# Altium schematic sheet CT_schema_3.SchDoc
size 208 x 169 mm
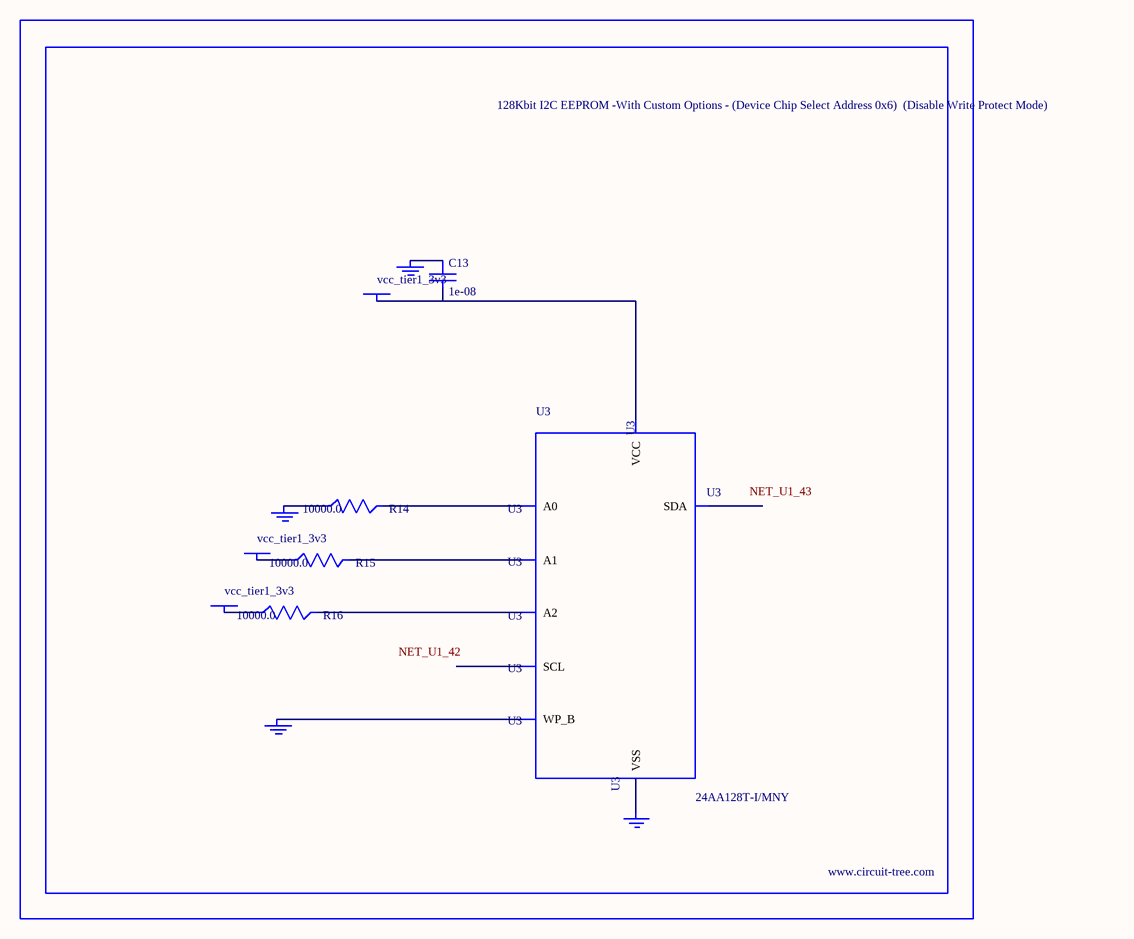
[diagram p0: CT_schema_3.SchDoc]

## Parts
BORDER2  (no value)
C13  1e-08  [C0402]
GND_INSTANCE_2_0  (no value)
GND_INSTANCE_2_1  (no value)
GND_INSTANCE_2_2  (no value)
GND_INSTANCE_2_3  (no value)
POWER_INSTANCE_2_0  vcc_tier1_3v3
POWER_INSTANCE_2_1  vcc_tier1_3v3
POWER_INSTANCE_2_2  vcc_tier1_3v3
R14  10000.0  [R0603]
R15  10000.0  [R0603]
R16  10000.0  [R0603]
U3  24AA128T-I/MNY  [TDFN-8/6MM]

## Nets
NetC13_1: C13.1 GND_INSTANCE_2_2.0(GND)
NetC13_2: C13.2 POWER_INSTANCE_2_2.0(PWR) U3.8(VCC)
NetGND_INSTANCE_2_0_0: GND_INSTANCE_2_0.0(GND) R14.1
NetGND_INSTANCE_2_1_0: GND_INSTANCE_2_1.0(GND) U3.7(WP_B)
NetGND_INSTANCE_2_3_0: GND_INSTANCE_2_3.0(GND) U3.4(VSS)
NetPOWER_INSTANCE_2_0_0: POWER_INSTANCE_2_0.0(PWR) R15.1
NetPOWER_INSTANCE_2_1_0: POWER_INSTANCE_2_1.0(PWR) R16.1
NetR14_2: R14.2 U3.1(A0)
NetR15_2: R15.2 U3.2(A1)
NetR16_2: R16.2 U3.3(A2)

Not connected (* = marked no-connect by the designer): U3 5(SDA) 6(SCL)

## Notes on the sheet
- Labels drawn without touching a wire or pin: NET_U1_42, NET_U1_43

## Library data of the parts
BORDER2 = BORDER_PAGE2
C13 = C0402C103K3RAC
GND_INSTANCE_2_0-GND_INSTANCE_2_3 = GND
POWER_INSTANCE_2_0-POWER_INSTANCE_2_2 = PWR
R14-R16 = RC0603JR-0710KL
